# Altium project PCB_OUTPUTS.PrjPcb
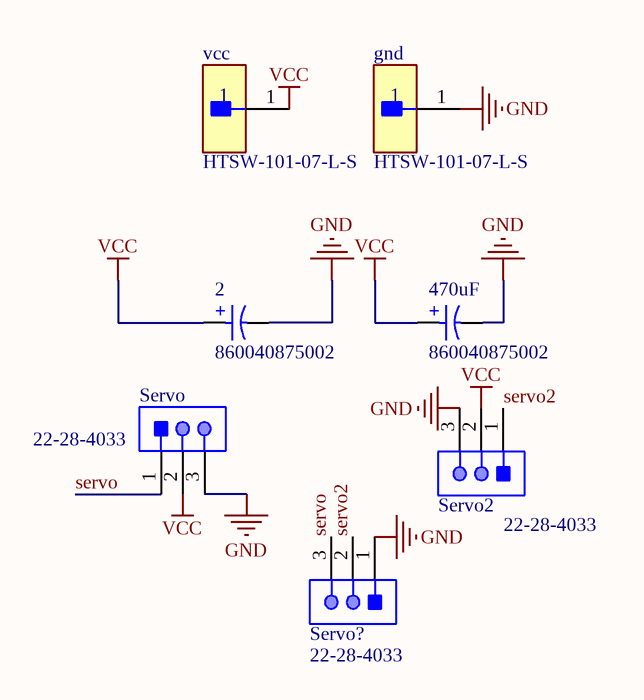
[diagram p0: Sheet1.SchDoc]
1 sheet, 7 parts. Net scope: global (net labels, ports and power ports of the same name join across sheets).
Board file: PCB1.PcbDoc

## Sheet Sheet1.SchDoc
size A4; SheetNumber: 1; SheetTotal: 1

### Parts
2  860040875002  [WCAP-ATUL_D10H12.5]
470uF  860040875002  [WCAP-ATUL_D10H12.5]
gnd  HTSW-101-07-L-S  [FP-HTSW-101-07-L-S-MFG]
Servo  22-28-4033  [MOLX-22-28-4033_V]
Servo2  22-28-4033  [MOLX-22-28-4033_V]
Servo?  22-28-4033  [MOLX-22-28-4033_V]
vcc  HTSW-101-07-L-S  [FP-HTSW-101-07-L-S-MFG]

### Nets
GND: 2.2(N) 470uF.2(N) gnd.1 Servo.3 Servo2.3 Servo?.1
VCC: 2.1(P) 470uF.1(P) Servo.2 Servo2.2 vcc.1
servo: Servo.1 Servo?.3
servo2: Servo2.1 Servo?.2

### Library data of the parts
2 470uF = CMP-03913-53914322-1: 860040875002 WCAP-ATUL Aluminum Electrolytic Capacitors; Pitch: 5mm; Voltage Rating: 100V; Tolerance: 20%; Polarity: Polar; Ripple Current: 400mA; Capacitance: 47µF; Life (Hours): 7000hours; Leakage Current: 47µA; Impedance: 420mΩ
gnd vcc = CMP-02766-001464-1: CONN HEADER VERT 1POS; Number of Contacts: 1; Max Voltage Rating (AC): 550V; Gender: Male; Max Current Rating: 7.6A
Servo Servo2 Servo? = CMP-1676-00001-5: Male Header, Pitch 2.54 mm, 1 x 3 Position, Height 8.38 mm, Tail Length 3.18 mm, RoHS, Bulk; Manufacturer: Molex; Rows: 1; Voltage Rating: 250 V; Current Rating: 4 A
